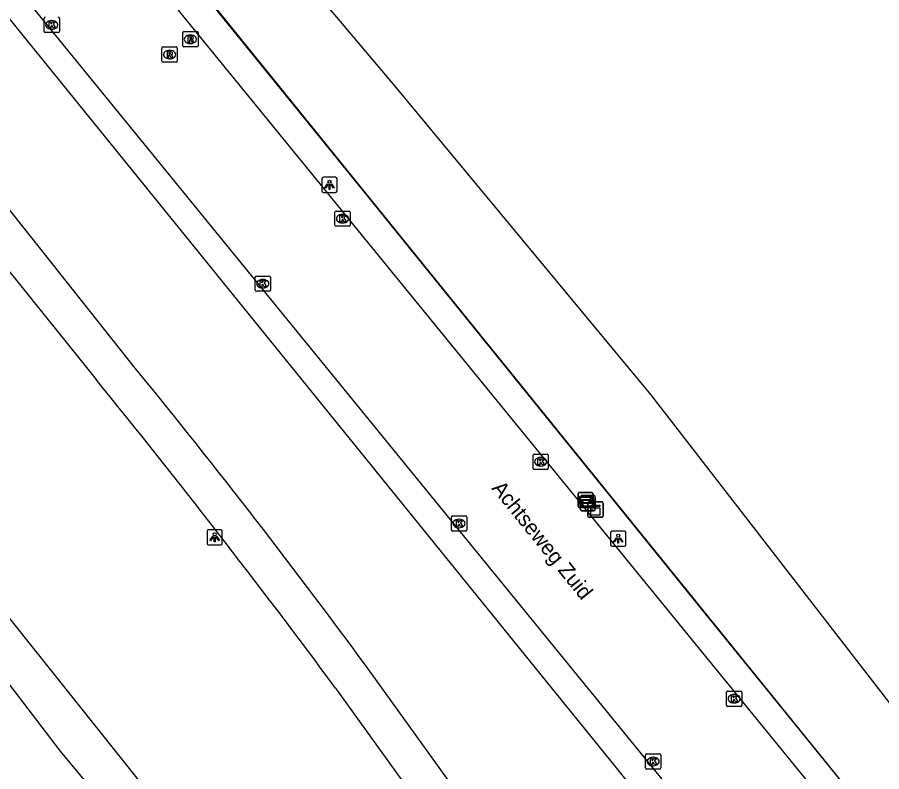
# Model space of a CAD drawing. Extents: x 157154 to 159278, y 385000 to 386650.
# Drawn here: x 158879.8 to 158936.6, y 385669 to 385718.6 of the extents above; entities that cross this region are included whole.
import ezdxf

# ---------------------------------------------------------------- set-up
doc = ezdxf.new("R2010")
doc.units = 0
for name, color, linetype in [('IMGEO_Fietspad_gesloten', 7, 'Continuous'), ('IMGEO_Gemengd_bos', 7, 'Continuous'), ('IMGEO_Grasland_overig', 7, 'Continuous'), ('IMGEO_Hek', 7, 'Continuous'), ('IMGEO_Kast', 7, 'Continuous'), ('IMGEO_Kolk', 7, 'Continuous'), ('IMGEO_Lichtpunt', 7, 'Continuous'), ('IMGEO_Openbare_ruimte_label', 7, 'Continuous'), ('IMGEO_Rijbaan_lokaal_open', 7, 'Continuous'), ('IMGEO_Rioolput', 7, 'Continuous'), ('IMGEO_Spoorbaan_halfverhard', 7, 'Continuous'), ('IMGEO_Verklikker', 7, 'Continuous')]:
    doc.layers.add(name, color=color, linetype=linetype)

msp = doc.modelspace()

# ---------------------------------------------------------------- linework, layer by layer
at = {"layer": 'IMGEO_Fietspad_gesloten'}
for points in [[(158887.032, 385696.203), (158875.776, 385710.384), (158870.44, 385717.022)], [(158868.92, 385714.89), (158873.543, 385709.084), (158879.044, 385702.219), (158884.968, 385694.825)], [(158927.782, 385640.591), (158925.153, 385644.607), (158921.814, 385649.468), (158902.682, 385676.049)], [(158900.712, 385674.546), (158919.812, 385648.003), (158923.006, 385643.324), (158924.763, 385640.654), (158926.139, 385638.563)]]:
    msp.add_lwpolyline(points, dxfattribs=at)
for centre, radius, start, end in [((158519.057, 385394.31), 475.967, 36.29407, 39.36609), ((158461.124, 385349.514), 546.702, 36.47925, 39.17011)]:
    msp.add_arc(centre, radius, start, end, dxfattribs=at)
at = {"layer": 'IMGEO_Gemengd_bos'}
for points in [[(158932.312, 385652.515), (158919.473, 385668.949), (158855.198, 385748.283), (158846.978, 385758.429)], [(158921.805, 385632.158), (158919.853, 385633.856), (158913.298, 385639.803), (158906.533, 385646.462), (158902.809, 385650.392), (158893.72, 385661.044), (158872.114, 385688.095)], [(158919.988, 385630.429), (158904.058, 385645.478), (158896.731, 385653.396), (158882.636, 385670.392), (158869.426, 385687.65)]]:
    msp.add_lwpolyline(points, dxfattribs=at)
at = {"layer": 'IMGEO_Grasland_overig'}
msp.add_lwpolyline([(158857.155, 385763.115), (158885.494, 385728.344), (159000, 385586.793), (159010.937, 385573.296), (159011.046, 385573.162)], dxfattribs=at)
at = {"layer": 'IMGEO_Hek'}
msp.add_lwpolyline([(159004.672, 385581.054), (158979.577, 385611.994), (158960.792, 385635.337), (158952.957, 385645.022), (158924.687, 385679.864), (158902.718, 385707.009), (158894.893, 385716.671), (158883.878, 385730.268), (158857.155, 385763.115), (158855.09, 385765.648), (158842.184, 385781.484), (158841.489, 385782.337), (158835.15, 385790.114), (158833.52, 385792.037), (158829.001, 385797.593), (158817.976, 385811.106), (158808.477, 385822.704)], dxfattribs=at)
at = {"layer": 'IMGEO_Kast'}
for p, q in [((158917.304, 385685.858), (158917.304, 385686.699)), ((158917.304, 385686.699), (158917.304, 385685.858)), ((158917.379, 385686.783), (158918.22, 385686.783)), ((158918.22, 385686.783), (158917.379, 385686.783)), ((158918.304, 385686.708), (158918.304, 385685.867)), ((158918.304, 385685.867), (158918.304, 385686.708)), ((158918.229, 385685.783), (158917.388, 385685.783)), ((158917.388, 385685.783), (158918.229, 385685.783))]:
    msp.add_line(p, q, dxfattribs=at)
for points in [[(158917.499, 385686.573), (158918.099, 385686.573), (158918.099, 385686.488), (158917.499, 385686.488), (158917.499, 385686.573)], [(158917.499, 385686.398), (158918.099, 385686.398), (158918.099, 385685.909), (158917.499, 385685.909), (158917.499, 385686.398)]]:
    msp.add_lwpolyline(points, dxfattribs=at)
msp.add_circle((158917.583, 385686.247), 0.0377, dxfattribs=at)
for centre, start, end in [((158917.382, 385686.705), 92.4484, 184.2845), ((158917.382, 385686.705), 92.4484, 184.2845), ((158918.226, 385686.705), 2.4484, 94.2845), ((158918.226, 385686.705), 2.4484, 94.2845), ((158917.382, 385685.861), 182.4484, 274.2845), ((158917.382, 385685.861), 182.4484, 274.2845), ((158918.226, 385685.861), 272.4484, 4.2845), ((158918.226, 385685.861), 272.4484, 4.2845)]:
    msp.add_arc(centre, 0.0779, start, end, dxfattribs=at)
at = {"layer": 'IMGEO_Kolk'}
for p, q in [((158881.553, 385717.72), (158881.553, 385718.572)), ((158882.041, 385718.426), (158882.066, 385718.426)), ((158882.554, 385718.572), (158882.554, 385717.72)), ((158882.48, 385717.646), (158881.628, 385717.646)), ((158882.064, 385717.866), (158882.039, 385717.866)), ((158900.674, 385704.98), (158900.674, 385705.832)), ((158900.749, 385705.906), (158901.601, 385705.906)), ((158901.162, 385705.686), (158901.187, 385705.686)), ((158901.675, 385705.832), (158901.675, 385704.98)), ((158901.185, 385705.126), (158901.16, 385705.126)), ((158901.601, 385704.906), (158900.749, 385704.906)), ((158895.505, 385701.63), (158896.357, 385701.63)), ((158895.43, 385700.704), (158895.43, 385701.556)), ((158895.918, 385701.41), (158895.943, 385701.41)), ((158896.431, 385701.556), (158896.431, 385700.704)), ((158896.357, 385700.63), (158895.505, 385700.63)), ((158895.941, 385700.85), (158895.916, 385700.85)), ((158913.699, 385688.998), (158913.699, 385689.85)), ((158913.774, 385689.924), (158914.626, 385689.924)), ((158914.187, 385689.704), (158914.212, 385689.704)), ((158914.7, 385689.85), (158914.7, 385688.998)), ((158914.21, 385689.144), (158914.185, 385689.144)), ((158914.626, 385688.924), (158913.774, 385688.924)), ((158908.335, 385684.939), (158908.335, 385685.791)), ((158908.41, 385685.865), (158909.262, 385685.865)), ((158909.336, 385685.791), (158909.336, 385684.939)), ((158908.823, 385685.645), (158908.848, 385685.645)), ((158909.262, 385684.865), (158908.41, 385684.865)), ((158908.846, 385685.085), (158908.821, 385685.085)), ((158926.494, 385674.342), (158927.346, 385674.342)), ((158926.419, 385673.416), (158926.419, 385674.268)), ((158926.907, 385674.122), (158926.932, 385674.122)), ((158927.42, 385674.268), (158927.42, 385673.416)), ((158927.346, 385673.342), (158926.494, 385673.342)), ((158926.93, 385673.562), (158926.905, 385673.562)), ((158921.095, 385669.29), (158921.095, 385670.142)), ((158921.17, 385670.216), (158922.022, 385670.216)), ((158921.583, 385669.996), (158921.608, 385669.996)), ((158922.096, 385670.142), (158922.096, 385669.29)), ((158922.022, 385669.216), (158921.17, 385669.216)), ((158921.606, 385669.436), (158921.581, 385669.436))]:
    msp.add_line(p, q, dxfattribs=at)
for points in [[(158881.553, 385717.72), (158881.553, 385718.572)], [(158881.874, 385718.346), (158881.997, 385718.346), (158881.997, 385718.195), (158882.127, 385718.346), (158882.291, 385718.346), (158882.145, 385718.195), (158882.298, 385717.946), (158882.146, 385717.946), (158882.061, 385718.11), (158881.997, 385718.043), (158881.997, 385717.946), (158881.874, 385717.946), (158881.874, 385718.346)], [(158882.554, 385718.572), (158882.554, 385717.72)], [(158882.48, 385717.646), (158881.628, 385717.646)], [(158900.674, 385704.98), (158900.674, 385705.832)], [(158900.749, 385705.906), (158901.601, 385705.906)], [(158900.995, 385705.606), (158901.118, 385705.606), (158901.118, 385705.455), (158901.248, 385705.606), (158901.412, 385705.606), (158901.266, 385705.455), (158901.419, 385705.206), (158901.267, 385705.206), (158901.182, 385705.37), (158901.118, 385705.303), (158901.118, 385705.206), (158900.995, 385705.206), (158900.995, 385705.606)], [(158901.675, 385705.832), (158901.675, 385704.98)], [(158901.601, 385704.906), (158900.749, 385704.906)], [(158895.505, 385701.63), (158896.357, 385701.63)], [(158895.43, 385700.704), (158895.43, 385701.556)], [(158895.751, 385701.33), (158895.874, 385701.33), (158895.874, 385701.179), (158896.004, 385701.33), (158896.168, 385701.33), (158896.022, 385701.179), (158896.175, 385700.93), (158896.023, 385700.93), (158895.938, 385701.094), (158895.874, 385701.027), (158895.874, 385700.93), (158895.751, 385700.93), (158895.751, 385701.33)], [(158896.431, 385701.556), (158896.431, 385700.704)], [(158896.357, 385700.63), (158895.505, 385700.63)], [(158913.699, 385688.998), (158913.699, 385689.85)], [(158913.774, 385689.924), (158914.626, 385689.924)], [(158914.7, 385689.85), (158914.7, 385688.998)], [(158914.02, 385689.624), (158914.143, 385689.624), (158914.143, 385689.473), (158914.273, 385689.624), (158914.437, 385689.624), (158914.291, 385689.473), (158914.444, 385689.224), (158914.292, 385689.224), (158914.207, 385689.388), (158914.143, 385689.321), (158914.143, 385689.224), (158914.02, 385689.224), (158914.02, 385689.624)], [(158914.626, 385688.924), (158913.774, 385688.924)], [(158908.335, 385684.939), (158908.335, 385685.791)], [(158908.41, 385685.865), (158909.262, 385685.865)], [(158909.336, 385685.791), (158909.336, 385684.939)], [(158908.656, 385685.565), (158908.779, 385685.565), (158908.779, 385685.414), (158908.909, 385685.565), (158909.073, 385685.565), (158908.927, 385685.414), (158909.08, 385685.165), (158908.928, 385685.165), (158908.843, 385685.329), (158908.779, 385685.262), (158908.779, 385685.165), (158908.656, 385685.165), (158908.656, 385685.565)], [(158909.262, 385684.865), (158908.41, 385684.865)], [(158926.494, 385674.342), (158927.346, 385674.342)], [(158926.419, 385673.416), (158926.419, 385674.268)], [(158926.74, 385674.042), (158926.863, 385674.042), (158926.863, 385673.891), (158926.993, 385674.042), (158927.157, 385674.042), (158927.011, 385673.891), (158927.164, 385673.642), (158927.012, 385673.642), (158926.927, 385673.806), (158926.863, 385673.739), (158926.863, 385673.642), (158926.74, 385673.642), (158926.74, 385674.042)], [(158927.42, 385674.268), (158927.42, 385673.416)], [(158927.346, 385673.342), (158926.494, 385673.342)], [(158921.095, 385669.29), (158921.095, 385670.142)], [(158921.17, 385670.216), (158922.022, 385670.216)], [(158921.416, 385669.916), (158921.539, 385669.916), (158921.539, 385669.765), (158921.669, 385669.916), (158921.833, 385669.916), (158921.687, 385669.765), (158921.84, 385669.516), (158921.688, 385669.516), (158921.603, 385669.68), (158921.539, 385669.613), (158921.539, 385669.516), (158921.416, 385669.516), (158921.416, 385669.916)], [(158922.096, 385670.142), (158922.096, 385669.29)], [(158922.022, 385669.216), (158921.17, 385669.216)]]:
    msp.add_lwpolyline(points, dxfattribs=at)
for centre, start, end in [((158881.63, 385718.57), 91.552, 178.448), ((158881.63, 385718.57), 91.552, 178.448), ((158882.478, 385718.57), 1.552, 88.448), ((158882.478, 385718.57), 1.552, 88.448), ((158881.63, 385717.722), 181.552, 268.448), ((158881.63, 385717.722), 181.552, 268.448), ((158882.478, 385717.722), 271.552, 358.448), ((158882.478, 385717.722), 271.552, 358.448), ((158900.751, 385705.83), 91.552, 178.448), ((158900.751, 385705.83), 91.552, 178.448), ((158901.599, 385705.83), 1.552, 88.448), ((158901.599, 385705.83), 1.552, 88.448), ((158900.751, 385704.982), 181.552, 268.448), ((158900.751, 385704.982), 181.552, 268.448), ((158901.599, 385704.982), 271.552, 358.448), ((158901.599, 385704.982), 271.552, 358.448), ((158895.507, 385701.554), 91.552, 178.448), ((158895.507, 385701.554), 91.552, 178.448), ((158896.355, 385701.554), 1.552, 88.448), ((158896.355, 385701.554), 1.552, 88.448), ((158895.507, 385700.706), 181.552, 268.448), ((158895.507, 385700.706), 181.552, 268.448), ((158896.355, 385700.706), 271.552, 358.448), ((158896.355, 385700.706), 271.552, 358.448), ((158913.776, 385689.848), 91.552, 178.448), ((158913.776, 385689.848), 91.552, 178.448), ((158914.624, 385689.848), 1.552, 88.448), ((158914.624, 385689.848), 1.552, 88.448), ((158913.776, 385689), 181.552, 268.448), ((158913.776, 385689), 181.552, 268.448), ((158914.624, 385689), 271.552, 358.448), ((158914.624, 385689), 271.552, 358.448), ((158908.412, 385685.789), 91.552, 178.448), ((158908.412, 385685.789), 91.552, 178.448), ((158909.26, 385685.789), 1.552, 88.448), ((158909.26, 385685.789), 1.552, 88.448), ((158908.412, 385684.941), 181.552, 268.448), ((158908.412, 385684.941), 181.552, 268.448), ((158909.26, 385684.941), 271.552, 358.448), ((158909.26, 385684.941), 271.552, 358.448), ((158926.496, 385674.266), 91.552, 178.448), ((158926.496, 385674.266), 91.552, 178.448), ((158927.344, 385674.266), 1.552, 88.448), ((158927.344, 385674.266), 1.552, 88.448), ((158926.496, 385673.418), 181.552, 268.448), ((158926.496, 385673.418), 181.552, 268.448), ((158927.344, 385673.418), 271.552, 358.448), ((158927.344, 385673.418), 271.552, 358.448), ((158921.172, 385670.14), 91.552, 178.448), ((158921.172, 385670.14), 91.552, 178.448), ((158922.02, 385670.14), 1.552, 88.448), ((158922.02, 385670.14), 1.552, 88.448), ((158921.172, 385669.292), 181.552, 268.448), ((158921.172, 385669.292), 181.552, 268.448), ((158922.02, 385669.292), 271.552, 358.448), ((158922.02, 385669.292), 271.552, 358.448)]:
    msp.add_arc(centre, 0.0765, start, end, dxfattribs=at)
for centre, major_axis, ratio, start_param, end_param in [((158882.04, 385718.146), (-0.387, 0.002), 0.722429, 4.712389, 7.853982), ((158882.065, 385718.146), (-0.39, 0.002), 0.717154, 1.570796, 4.712389), ((158901.161, 385705.406), (-0.387, 0.002), 0.722429, 4.712389, 7.853982), ((158901.186, 385705.406), (-0.39, 0.002), 0.717154, 1.570796, 4.712389), ((158895.917, 385701.13), (-0.387, 0.002), 0.722429, 4.712389, 7.853982), ((158895.942, 385701.13), (-0.39, 0.002), 0.717154, 1.570796, 4.712389), ((158914.186, 385689.424), (-0.387, 0.002), 0.722429, 4.712389, 7.853982), ((158914.211, 385689.424), (-0.39, 0.002), 0.717154, 1.570796, 4.712389), ((158908.822, 385685.365), (-0.387, 0.002), 0.722429, 4.712389, 7.853982), ((158908.847, 385685.365), (-0.39, 0.002), 0.717154, 1.570796, 4.712389), ((158926.906, 385673.842), (-0.387, 0.002), 0.722429, 4.712389, 7.853982), ((158926.931, 385673.842), (-0.39, 0.002), 0.717154, 1.570796, 4.712389), ((158921.582, 385669.716), (-0.387, 0.002), 0.722429, 4.712389, 7.853982), ((158921.607, 385669.716), (-0.39, 0.002), 0.717154, 1.570796, 4.712389)]:
    msp.add_ellipse(centre, major_axis=major_axis, ratio=ratio, start_param=start_param, end_param=end_param, dxfattribs=at)
at = {"layer": 'IMGEO_Lichtpunt'}
for p, q in [((158899.817, 385708.034), (158899.817, 385707.227)), ((158899.817, 385708.034), (158899.817, 385707.227)), ((158900.719, 385708.129), (158899.911, 385708.129)), ((158900.719, 385708.129), (158899.911, 385708.129)), ((158900.813, 385707.227), (158900.813, 385708.034)), ((158900.813, 385707.227), (158900.813, 385708.034)), ((158899.911, 385707.133), (158900.719, 385707.133)), ((158899.911, 385707.133), (158900.719, 385707.133)), ((158892.266, 385684.858), (158892.266, 385684.051)), ((158892.266, 385684.858), (158892.266, 385684.051)), ((158893.168, 385684.953), (158892.36, 385684.953)), ((158893.168, 385684.953), (158892.36, 385684.953)), ((158893.262, 385684.051), (158893.262, 385684.858)), ((158893.262, 385684.051), (158893.262, 385684.858)), ((158918.802, 385684.768), (158918.802, 385683.961)), ((158918.802, 385684.768), (158918.802, 385683.961)), ((158919.704, 385684.863), (158918.896, 385684.863)), ((158919.704, 385684.863), (158918.896, 385684.863)), ((158919.798, 385683.961), (158919.798, 385684.768)), ((158919.798, 385683.961), (158919.798, 385684.768)), ((158892.36, 385683.957), (158893.168, 385683.957)), ((158892.36, 385683.957), (158893.168, 385683.957)), ((158918.896, 385683.867), (158919.704, 385683.867)), ((158918.896, 385683.867), (158919.704, 385683.867))]:
    msp.add_line(p, q, dxfattribs=at)
for points in [[(158900.191, 385707.698), (158900.23, 385707.67), (158900.042, 385707.408), (158900.004, 385707.435), (158900.191, 385707.698)], [(158900.293, 385707.65), (158900.34, 385707.65), (158900.34, 385707.328), (158900.293, 385707.328), (158900.293, 385707.65)], [(158900.403, 385707.67), (158900.441, 385707.697), (158900.628, 385707.435), (158900.589, 385707.407), (158900.403, 385707.67)], [(158892.64, 385684.522), (158892.679, 385684.494), (158892.491, 385684.232), (158892.453, 385684.259), (158892.64, 385684.522)], [(158892.742, 385684.474), (158892.789, 385684.474), (158892.789, 385684.152), (158892.742, 385684.152), (158892.742, 385684.474)], [(158892.852, 385684.494), (158892.89, 385684.521), (158893.077, 385684.259), (158893.038, 385684.231), (158892.852, 385684.494)], [(158919.176, 385684.432), (158919.215, 385684.404), (158919.027, 385684.142), (158918.989, 385684.169), (158919.176, 385684.432)], [(158919.278, 385684.384), (158919.325, 385684.384), (158919.325, 385684.062), (158919.278, 385684.062), (158919.278, 385684.384)], [(158919.388, 385684.404), (158919.426, 385684.431), (158919.613, 385684.169), (158919.574, 385684.141), (158919.388, 385684.404)]]:
    msp.add_lwpolyline(points, dxfattribs=at)
for centre in [(158900.316, 385707.832), (158892.765, 385684.656), (158919.301, 385684.566)]:
    msp.add_circle(centre, 0.0994, dxfattribs=at)
for centre, start, end in [((158899.911, 385708.034), 90, 180), ((158899.911, 385708.034), 90, 180), ((158900.719, 385708.034), 0, 90), ((158900.719, 385708.034), 0, 90), ((158899.911, 385707.227), 180, 270), ((158899.911, 385707.227), 180, 270), ((158900.719, 385707.227), 270, 0), ((158900.719, 385707.227), 270, 360), ((158892.36, 385684.858), 90, 180), ((158892.36, 385684.858), 90, 180), ((158893.168, 385684.858), 0, 90), ((158893.168, 385684.858), 0, 90), ((158918.896, 385684.768), 90, 180), ((158918.896, 385684.768), 90, 180), ((158919.704, 385684.768), 0, 90), ((158919.704, 385684.768), 0, 90), ((158892.36, 385684.051), 180, 270), ((158892.36, 385684.051), 180, 270), ((158893.168, 385684.051), 270, 0), ((158893.168, 385684.051), 270, 360), ((158918.896, 385683.961), 180, 270), ((158918.896, 385683.961), 180, 270), ((158919.704, 385683.961), 270, 0), ((158919.704, 385683.961), 270, 360)]:
    msp.add_arc(centre, 0.0946, start, end, dxfattribs=at)
at = {"layer": 'IMGEO_Rijbaan_lokaal_open'}
for points in [[(158854.381, 385763.213), (159043.862, 385530.978), (159167.844, 385378.971)], [(158935.542, 385652.189), (158848.245, 385759.247)]]:
    msp.add_lwpolyline(points, dxfattribs=at)
at = {"layer": 'IMGEO_Rioolput'}
for p, q in [((158890.669, 385716.777), (158890.669, 385717.629)), ((158890.744, 385717.703), (158891.596, 385717.703)), ((158891.67, 385717.629), (158891.67, 385716.777)), ((158891.18, 385716.923), (158891.155, 385716.923)), ((158891.157, 385717.483), (158891.182, 385717.483)), ((158889.299, 385715.77), (158889.299, 385716.622)), ((158889.374, 385716.696), (158890.226, 385716.696)), ((158889.787, 385716.476), (158889.812, 385716.476)), ((158890.3, 385716.622), (158890.3, 385715.77)), ((158891.596, 385716.703), (158890.744, 385716.703)), ((158889.81, 385715.916), (158889.785, 385715.916)), ((158890.226, 385715.696), (158889.374, 385715.696))]:
    msp.add_line(p, q, dxfattribs=at)
for points in [[(158890.669, 385716.777), (158890.669, 385717.629)], [(158890.744, 385717.703), (158891.596, 385717.703)], [(158891.67, 385717.629), (158891.67, 385716.777)], [(158891.258, 385717.401), (158891.006, 385717.403), (158891.006, 385717.003)], [(158891.006, 385717.003), (158891.13, 385717.003), (158891.13, 385717.165), (158891.141, 385717.165)], [(158891.184, 385717.322), (158891.13, 385717.322), (158891.13, 385717.241)], [(158891.13, 385717.241), (158891.182, 385717.241)], [(158891.188, 385717.136), (158891.259, 385717.003), (158891.399, 385717.003), (158891.334, 385717.129)], [(158889.299, 385715.77), (158889.299, 385716.622)], [(158889.374, 385716.696), (158890.226, 385716.696)], [(158889.888, 385716.394), (158889.636, 385716.396), (158889.636, 385715.996)], [(158890.3, 385716.622), (158890.3, 385715.77)], [(158891.596, 385716.703), (158890.744, 385716.703)], [(158889.636, 385715.996), (158889.76, 385715.996), (158889.76, 385716.158), (158889.771, 385716.158)], [(158889.814, 385716.315), (158889.76, 385716.315), (158889.76, 385716.234)], [(158889.76, 385716.234), (158889.812, 385716.234)], [(158889.818, 385716.129), (158889.889, 385715.996), (158890.029, 385715.996), (158889.964, 385716.122)], [(158890.226, 385715.696), (158889.374, 385715.696)]]:
    msp.add_lwpolyline(points, dxfattribs=at)
for centre, radius, start, end in [((158890.746, 385717.627), 0.0765, 91.552, 178.448), ((158890.746, 385717.627), 0.0765, 91.552, 178.448), ((158891.594, 385717.627), 0.0765, 1.552, 88.448), ((158891.594, 385717.627), 0.0765, 1.552, 88.448), ((158891.14, 385717.112), 0.0533, 26.0293, 88.6989), ((158891.166, 385717.43), 0.19, 274.7715, 282.9687), ((158891.19, 385717.226), 0.0964, 77.0061, 93.1865), ((158891.204, 385717.283), 0.0378, 276.6634, 79.6772), ((158891.257, 385717.291), 0.109, 350.3612, 89.416), ((158891.255, 385717.291), 0.112, 277.5842, 350.9817), ((158891.239, 385717.076), 0.108, 29.5134, 73.7905), ((158889.376, 385716.62), 0.0765, 91.552, 178.448), ((158889.376, 385716.62), 0.0765, 91.552, 178.448), ((158889.887, 385716.284), 0.109, 350.3612, 89.416), ((158890.224, 385716.62), 0.0765, 1.552, 88.448), ((158890.224, 385716.62), 0.0765, 1.552, 88.448), ((158890.746, 385716.779), 0.0765, 181.552, 268.448), ((158890.746, 385716.779), 0.0765, 181.552, 268.448), ((158891.594, 385716.779), 0.0765, 271.552, 358.448), ((158891.594, 385716.779), 0.0765, 271.552, 358.448), ((158889.77, 385716.105), 0.0533, 26.0293, 88.6989), ((158889.796, 385716.423), 0.19, 274.7715, 282.9687), ((158889.82, 385716.219), 0.0964, 77.0061, 93.1865), ((158889.834, 385716.276), 0.0378, 276.6634, 79.6772), ((158889.885, 385716.284), 0.112, 277.5842, 350.9817), ((158889.869, 385716.069), 0.108, 29.5134, 73.7905), ((158889.376, 385715.772), 0.0765, 181.552, 268.448), ((158889.376, 385715.772), 0.0765, 181.552, 268.448), ((158890.224, 385715.772), 0.0765, 271.552, 358.448), ((158890.224, 385715.772), 0.0765, 271.552, 358.448)]:
    msp.add_arc(centre, radius, start, end, dxfattribs=at)
for centre, major_axis, ratio, start_param, end_param in [((158891.156, 385717.203), (-0.387, 0.002), 0.722429, 4.712389, 7.853982), ((158891.181, 385717.203), (-0.39, 0.002), 0.717154, 1.570796, 4.712389), ((158889.786, 385716.196), (-0.387, 0.002), 0.722429, 4.712389, 7.853982), ((158889.811, 385716.196), (-0.39, 0.002), 0.717154, 1.570796, 4.712389)]:
    msp.add_ellipse(centre, major_axis=major_axis, ratio=ratio, start_param=start_param, end_param=end_param, dxfattribs=at)
at = {"layer": 'IMGEO_Spoorbaan_halfverhard'}
msp.add_lwpolyline([(158861.769, 385765.386), (158874.506, 385750.091), (158887.558, 385734.319), (158904.599, 385714.138), (158921.424, 385693.853), (158944.372, 385664.217), (158959.648, 385644.849), (158984.94, 385614.139), (159014.573, 385576.309)], dxfattribs=at)
at = {"layer": 'IMGEO_Verklikker'}
for p, q in [((158916.755, 385687.405), (158917.545, 385687.405)), ((158917.545, 385687.405), (158916.755, 385687.405)), ((158916.655, 385686.505), (158916.655, 385687.305)), ((158916.655, 385687.305), (158916.655, 385686.505)), ((158916.804, 385686.301), (158916.804, 385687.101)), ((158916.804, 385687.101), (158916.804, 385686.301)), ((158916.904, 385687.201), (158917.694, 385687.201)), ((158917.694, 385687.201), (158916.904, 385687.201)), ((158917.645, 385687.305), (158917.645, 385686.505)), ((158917.645, 385686.505), (158917.645, 385687.305)), ((158917.794, 385687.101), (158917.794, 385686.301)), ((158917.794, 385686.301), (158917.794, 385687.101)), ((158917.545, 385686.405), (158916.755, 385686.405)), ((158916.755, 385686.405), (158917.545, 385686.405)), ((158917.694, 385686.201), (158916.904, 385686.201)), ((158916.904, 385686.201), (158917.694, 385686.201))]:
    msp.add_line(p, q, dxfattribs=at)
for points in [[(158916.756, 385687.137), (158917.544, 385687.137), (158917.544, 385686.673), (158916.756, 385686.673), (158916.756, 385687.137)], [(158916.821, 385687.072), (158916.821, 385686.738), (158917.479, 385686.738), (158917.479, 385687.072), (158916.821, 385687.072)], [(158916.905, 385686.933), (158917.693, 385686.933), (158917.693, 385686.469), (158916.905, 385686.469), (158916.905, 385686.933)], [(158916.97, 385686.868), (158916.97, 385686.534), (158917.628, 385686.534), (158917.628, 385686.868), (158916.97, 385686.868)]]:
    msp.add_lwpolyline(points, dxfattribs=at)
for centre, start, end in [((158916.755, 385687.305), 90, 180), ((158916.755, 385687.305), 90, 180), ((158917.545, 385687.305), 0, 90), ((158917.545, 385687.305), 360, 90), ((158916.904, 385687.101), 90, 180), ((158916.904, 385687.101), 90, 180), ((158917.694, 385687.101), 0, 90), ((158917.694, 385687.101), 360, 90), ((158916.755, 385686.505), 180, 270), ((158916.755, 385686.505), 180, 270), ((158916.904, 385686.301), 180, 270), ((158916.904, 385686.301), 180, 270), ((158917.545, 385686.505), 270, 0), ((158917.545, 385686.505), 270, 0), ((158917.694, 385686.301), 270, 0), ((158917.694, 385686.301), 270, 0)]:
    msp.add_arc(centre, 0.1, start, end, dxfattribs=at)

# ---------------------------------------------------------------- texts
at = {"layer": 'IMGEO_Openbare_ruimte_label'}
msp.add_text('Achtseweg Zuid', height=1, rotation=308.955, dxfattribs=at).set_placement((158910.938, 385687.661))

doc.saveas('drawing.dxf')
